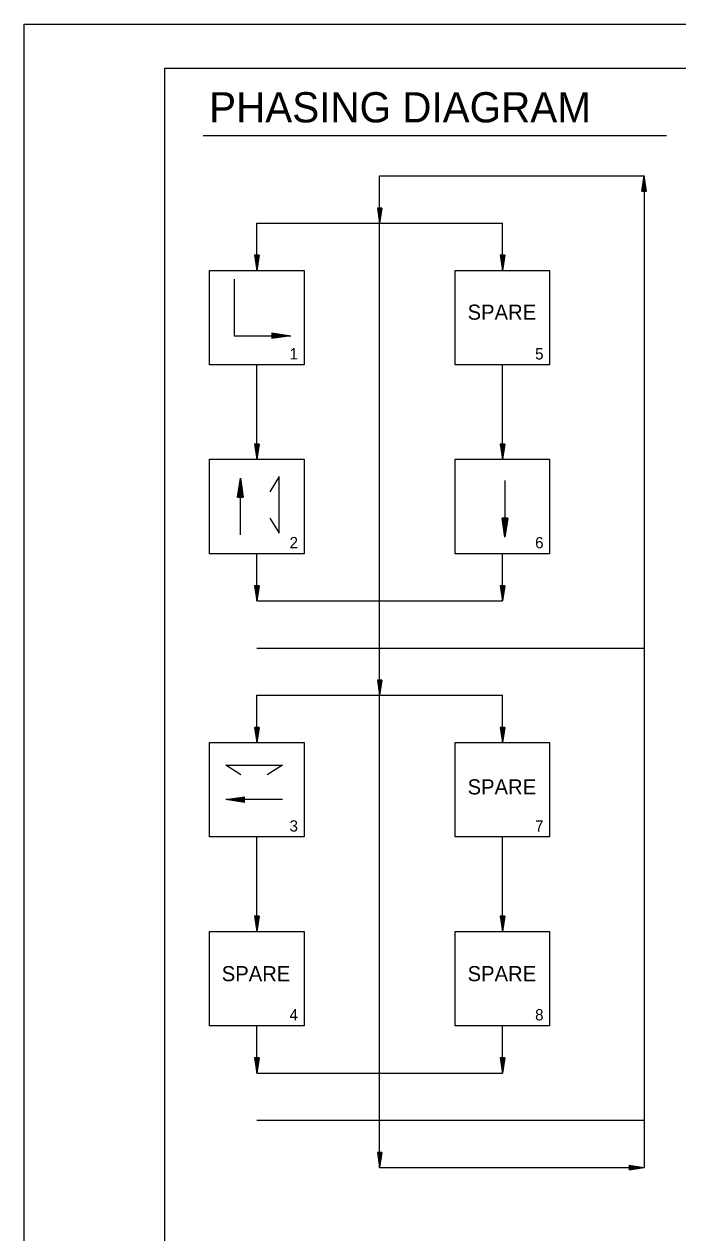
# Model space of a CAD drawing. Extents: x 1709451 to 1710451, y 561684 to 562324.
# Drawn here: x 1709451 to 1709624, y 562004 to 562324 of the extents above; entities that cross this region are included whole.
import ezdxf

# ---------------------------------------------------------------- set-up
doc = ezdxf.new("R2010")
doc.units = 0
for name, color, linetype in [('E_Existing ROW', 7, 'Continuous'), ('R_Alt Surface', 7, 'Continuous'), ('R_Alt Surface Annot', 7, 'Continuous'), ('R_Detour', 7, 'Continuous'), ('R_Detour Annot', 7, 'Continuous')]:
    doc.layers.add(name, color=color, linetype=linetype)

msp = doc.modelspace()

# ---------------------------------------------------------------- linework, layer by layer
at = {"layer": 'E_Existing ROW'}
for p, q in [((1709545.08, 562021.3), (1709545.08, 562283.8)), ((1709545.08, 562283.8), (1709615.08, 562283.8)), ((1709615.08, 562283.8), (1709615.08, 562021.3)), ((1709512.58, 562258.8), (1709512.58, 562271.3)), ((1709512.58, 562271.3), (1709577.58, 562271.3)), ((1709577.58, 562258.8), (1709577.58, 562271.3)), ((1709506.59, 562256.51), (1709506.59, 562241.51)), ((1709516.59, 562242.26), (1709521.59, 562241.51)), ((1709516.59, 562242.26), (1709516.59, 562240.76)), ((1709520.75, 562241.51), (1709516.59, 562242.14)), ((1709516.59, 562242.01), (1709519.89, 562241.51)), ((1709519.06, 562241.51), (1709516.59, 562241.88)), ((1709516.59, 562241.75), (1709518.21, 562241.51)), ((1709506.59, 562241.51), (1709521.59, 562241.51)), ((1709517.38, 562241.51), (1709516.59, 562241.63)), ((1709521.59, 562241.51), (1709516.59, 562240.76)), ((1709516.59, 562240.89), (1709520.75, 562241.51)), ((1709519.89, 562241.51), (1709516.59, 562241.01)), ((1709516.59, 562241.14), (1709519.06, 562241.51)), ((1709518.21, 562241.51), (1709516.59, 562241.27)), ((1709516.59, 562241.39), (1709517.38, 562241.51)), ((1709512.58, 562208.8), (1709512.58, 562233.8)), ((1709577.58, 562208.8), (1709577.58, 562233.8)), ((1709507.48, 562198.76), (1709508.23, 562203.76)), ((1709508.23, 562188.76), (1709508.23, 562203.76)), ((1709508.23, 562203.76), (1709508.98, 562198.76)), ((1709508.23, 562202.93), (1709507.61, 562198.76)), ((1709507.74, 562198.76), (1709508.23, 562202.07)), ((1709508.23, 562201.23), (1709507.86, 562198.76)), ((1709507.99, 562198.76), (1709508.23, 562200.39)), ((1709508.86, 562198.76), (1709508.23, 562202.93)), ((1709508.23, 562202.07), (1709508.73, 562198.76)), ((1709508.61, 562198.76), (1709508.23, 562201.23)), ((1709508.23, 562200.39), (1709508.48, 562198.76)), ((1709578.25, 562203.18), (1709578.25, 562188.18)), ((1709507.48, 562198.76), (1709508.98, 562198.76)), ((1709508.23, 562199.55), (1709508.12, 562198.76)), ((1709508.35, 562198.76), (1709508.23, 562199.55)), ((1709578.25, 562188.18), (1709577.5, 562193.18)), ((1709579, 562193.18), (1709577.5, 562193.18)), ((1709577.62, 562193.18), (1709578.25, 562189.02)), ((1709578.25, 562189.88), (1709577.75, 562193.18)), ((1709577.87, 562193.18), (1709578.25, 562190.71)), ((1709578.25, 562191.56), (1709578, 562193.18)), ((1709578.13, 562193.18), (1709578.25, 562192.39)), ((1709578.25, 562192.39), (1709578.36, 562193.18)), ((1709578.49, 562193.18), (1709578.25, 562191.56)), ((1709578.25, 562190.71), (1709578.62, 562193.18)), ((1709578.74, 562193.18), (1709578.25, 562189.88)), ((1709578.25, 562189.02), (1709578.87, 562193.18)), ((1709579, 562193.18), (1709578.25, 562188.18)), ((1709512.58, 562171.3), (1709512.58, 562183.8)), ((1709577.58, 562171.3), (1709577.58, 562183.8)), ((1709512.58, 562171.3), (1709577.58, 562171.3)), ((1709512.58, 562158.8), (1709615.08, 562158.8)), ((1709512.58, 562146.3), (1709577.58, 562146.3)), ((1709512.58, 562133.8), (1709512.58, 562146.3)), ((1709577.58, 562133.8), (1709577.58, 562146.3)), ((1709504.35, 562118.7), (1709509.35, 562119.45)), ((1709519.35, 562118.7), (1709504.35, 562118.7)), ((1709509.35, 562117.95), (1709504.35, 562118.7)), ((1709509.35, 562119.33), (1709505.19, 562118.7)), ((1709505.19, 562118.7), (1709509.35, 562118.08)), ((1709506.05, 562118.7), (1709509.35, 562119.2)), ((1709509.35, 562118.2), (1709506.05, 562118.7)), ((1709509.35, 562119.07), (1709506.88, 562118.7)), ((1709506.88, 562118.7), (1709509.35, 562118.33)), ((1709507.73, 562118.7), (1709509.35, 562118.95)), ((1709509.35, 562118.46), (1709507.73, 562118.7)), ((1709509.35, 562118.82), (1709508.56, 562118.7)), ((1709508.56, 562118.7), (1709509.35, 562118.58)), ((1709509.35, 562117.95), (1709509.35, 562119.45)), ((1709512.58, 562083.8), (1709512.58, 562108.8)), ((1709577.58, 562083.8), (1709577.58, 562108.8)), ((1709512.58, 562046.3), (1709512.58, 562058.8)), ((1709577.58, 562046.3), (1709577.58, 562058.8)), ((1709512.58, 562046.3), (1709577.58, 562046.3)), ((1709512.58, 562033.8), (1709615.08, 562033.8)), ((1709545.08, 562021.3), (1709615.08, 562021.3))]:
    msp.add_line(p, q, dxfattribs=at)
for points in [[(1709500.08, 562258.8), (1709525.08, 562258.8), (1709525.08, 562233.8), (1709500.08, 562233.8)], [(1709565.08, 562258.8), (1709590.08, 562258.8), (1709590.08, 562233.8), (1709565.08, 562233.8)], [(1709500.08, 562208.8), (1709525.08, 562208.8), (1709525.08, 562183.8), (1709500.08, 562183.8)], [(1709565.08, 562208.8), (1709590.08, 562208.8), (1709590.08, 562183.8), (1709565.08, 562183.8)], [(1709500.08, 562133.8), (1709525.08, 562133.8), (1709525.08, 562108.8), (1709500.08, 562108.8)], [(1709565.08, 562133.8), (1709590.08, 562133.8), (1709590.08, 562108.8), (1709565.08, 562108.8)], [(1709500.08, 562083.8), (1709525.08, 562083.8), (1709525.08, 562058.8), (1709500.08, 562058.8)], [(1709565.08, 562083.8), (1709590.08, 562083.8), (1709590.08, 562058.8), (1709565.08, 562058.8)]]:
    msp.add_lwpolyline(points, close=True, dxfattribs=at)
for points in [[(1709516.03, 562193.21), (1709518.53, 562189.21), (1709518.53, 562204.21), (1709516.03, 562200.21)], [(1709508.35, 562125.27), (1709504.35, 562127.77), (1709519.35, 562127.77), (1709515.35, 562125.27)]]:
    msp.add_lwpolyline(points, dxfattribs=at)
at = {"layer": 'R_Alt Surface'}
for p, q in [((1709488.22, 562312.31), (1710436.76, 562312.31)), ((1709488.22, 561695.93), (1709488.22, 562312.31))]:
    msp.add_line(p, q, dxfattribs=at)
at = {"layer": 'R_Alt Surface Annot'}
msp.add_line((1709451.02, 562324), (1710451.02, 562324), dxfattribs=at)
msp.add_lwpolyline([(1709451, 562324), (1710451.02, 562324), (1710451.02, 561683.98), (1709451, 561683.98)], close=True, dxfattribs=at)
at = {"layer": 'R_Detour'}
msp.add_line((1709498.35, 562294.52), (1709621, 562294.52), dxfattribs=at)
at = {"layer": 'R_Detour Annot'}
for p, q in [((1709614.48, 562279.8), (1709615.08, 562283.8)), ((1709615.68, 562279.8), (1709615.08, 562283.8)), ((1709614.58, 562279.8), (1709615.08, 562283.13)), ((1709614.68, 562279.8), (1709615.08, 562282.45)), ((1709614.78, 562279.8), (1709615.08, 562281.78)), ((1709614.88, 562279.8), (1709615.08, 562281.1)), ((1709614.98, 562279.8), (1709615.08, 562280.43)), ((1709615.58, 562279.8), (1709615.08, 562283.13)), ((1709615.47, 562279.8), (1709615.08, 562282.45)), ((1709615.37, 562279.8), (1709615.08, 562281.78)), ((1709615.27, 562279.8), (1709615.08, 562281.1)), ((1709615.17, 562279.8), (1709615.08, 562280.43)), ((1709614.48, 562279.8), (1709615.68, 562279.8)), ((1709544.48, 562275.3), (1709545.08, 562271.3)), ((1709545.68, 562275.3), (1709544.48, 562275.3)), ((1709544.58, 562275.3), (1709545.08, 562271.97)), ((1709544.68, 562275.3), (1709545.08, 562272.66)), ((1709544.78, 562275.3), (1709545.08, 562273.32)), ((1709544.88, 562275.3), (1709545.08, 562274)), ((1709544.98, 562275.3), (1709545.08, 562274.67)), ((1709545.68, 562275.3), (1709545.08, 562271.3)), ((1709545.27, 562275.3), (1709545.08, 562274)), ((1709545.47, 562275.3), (1709545.08, 562272.66)), ((1709545.58, 562275.3), (1709545.08, 562271.97)), ((1709545.37, 562275.3), (1709545.08, 562273.32)), ((1709545.17, 562275.3), (1709545.08, 562274.67)), ((1709511.98, 562262.8), (1709512.58, 562258.8)), ((1709513.18, 562262.8), (1709511.98, 562262.8)), ((1709512.08, 562262.8), (1709512.58, 562259.47)), ((1709512.18, 562262.8), (1709512.58, 562260.16)), ((1709512.28, 562262.8), (1709512.58, 562260.82)), ((1709512.38, 562262.8), (1709512.58, 562261.5)), ((1709512.48, 562262.8), (1709512.58, 562262.17)), ((1709513.18, 562262.8), (1709512.58, 562258.8)), ((1709512.77, 562262.8), (1709512.58, 562261.5)), ((1709512.97, 562262.8), (1709512.58, 562260.16)), ((1709513.08, 562262.8), (1709512.58, 562259.47)), ((1709512.87, 562262.8), (1709512.58, 562260.82)), ((1709512.67, 562262.8), (1709512.58, 562262.17)), ((1709576.98, 562262.8), (1709577.58, 562258.8)), ((1709578.18, 562262.8), (1709576.98, 562262.8)), ((1709577.08, 562262.8), (1709577.58, 562259.47)), ((1709577.18, 562262.8), (1709577.58, 562260.16)), ((1709577.28, 562262.8), (1709577.58, 562260.82)), ((1709577.38, 562262.8), (1709577.58, 562261.5)), ((1709577.48, 562262.8), (1709577.58, 562262.17)), ((1709578.18, 562262.8), (1709577.58, 562258.8)), ((1709577.77, 562262.8), (1709577.58, 562261.5)), ((1709577.97, 562262.8), (1709577.58, 562260.16)), ((1709578.08, 562262.8), (1709577.58, 562259.47)), ((1709577.87, 562262.8), (1709577.58, 562260.82)), ((1709577.67, 562262.8), (1709577.58, 562262.17)), ((1709511.98, 562212.8), (1709512.58, 562208.8)), ((1709513.18, 562212.8), (1709511.98, 562212.8)), ((1709512.08, 562212.8), (1709512.58, 562209.47)), ((1709512.18, 562212.8), (1709512.58, 562210.16)), ((1709512.28, 562212.8), (1709512.58, 562210.82)), ((1709512.38, 562212.8), (1709512.58, 562211.5)), ((1709512.48, 562212.8), (1709512.58, 562212.17)), ((1709513.18, 562212.8), (1709512.58, 562208.8)), ((1709512.77, 562212.8), (1709512.58, 562211.5)), ((1709512.97, 562212.8), (1709512.58, 562210.16)), ((1709513.08, 562212.8), (1709512.58, 562209.47)), ((1709512.87, 562212.8), (1709512.58, 562210.82)), ((1709512.67, 562212.8), (1709512.58, 562212.17)), ((1709576.98, 562212.8), (1709577.58, 562208.8)), ((1709578.18, 562212.8), (1709576.98, 562212.8)), ((1709577.08, 562212.8), (1709577.58, 562209.47)), ((1709577.18, 562212.8), (1709577.58, 562210.16)), ((1709577.28, 562212.8), (1709577.58, 562210.82)), ((1709577.38, 562212.8), (1709577.58, 562211.5)), ((1709577.48, 562212.8), (1709577.58, 562212.17)), ((1709578.18, 562212.8), (1709577.58, 562208.8)), ((1709577.77, 562212.8), (1709577.58, 562211.5)), ((1709577.97, 562212.8), (1709577.58, 562210.16)), ((1709578.08, 562212.8), (1709577.58, 562209.47)), ((1709577.87, 562212.8), (1709577.58, 562210.82)), ((1709577.67, 562212.8), (1709577.58, 562212.17)), ((1709511.98, 562175.3), (1709512.58, 562171.3)), ((1709513.18, 562175.3), (1709511.98, 562175.3)), ((1709512.08, 562175.3), (1709512.58, 562171.97)), ((1709512.18, 562175.3), (1709512.58, 562172.66)), ((1709512.28, 562175.3), (1709512.58, 562173.32)), ((1709512.38, 562175.3), (1709512.58, 562174)), ((1709512.48, 562175.3), (1709512.58, 562174.67)), ((1709513.18, 562175.3), (1709512.58, 562171.3)), ((1709512.77, 562175.3), (1709512.58, 562174)), ((1709512.97, 562175.3), (1709512.58, 562172.66)), ((1709513.08, 562175.3), (1709512.58, 562171.97)), ((1709512.87, 562175.3), (1709512.58, 562173.32)), ((1709512.67, 562175.3), (1709512.58, 562174.67)), ((1709576.98, 562175.3), (1709577.58, 562171.3)), ((1709578.18, 562175.3), (1709576.98, 562175.3)), ((1709577.08, 562175.3), (1709577.58, 562171.97)), ((1709577.18, 562175.3), (1709577.58, 562172.66)), ((1709577.28, 562175.3), (1709577.58, 562173.32)), ((1709577.38, 562175.3), (1709577.58, 562174)), ((1709577.48, 562175.3), (1709577.58, 562174.67)), ((1709578.18, 562175.3), (1709577.58, 562171.3)), ((1709577.77, 562175.3), (1709577.58, 562174)), ((1709577.97, 562175.3), (1709577.58, 562172.66)), ((1709578.08, 562175.3), (1709577.58, 562171.97)), ((1709577.87, 562175.3), (1709577.58, 562173.32)), ((1709577.67, 562175.3), (1709577.58, 562174.67)), ((1709544.48, 562150.3), (1709545.08, 562146.3)), ((1709545.68, 562150.3), (1709544.48, 562150.3)), ((1709544.58, 562150.3), (1709545.08, 562146.97)), ((1709544.68, 562150.3), (1709545.08, 562147.66)), ((1709544.78, 562150.3), (1709545.08, 562148.32)), ((1709544.88, 562150.3), (1709545.08, 562149)), ((1709544.98, 562150.3), (1709545.08, 562149.67)), ((1709545.68, 562150.3), (1709545.08, 562146.3)), ((1709545.27, 562150.3), (1709545.08, 562149)), ((1709545.47, 562150.3), (1709545.08, 562147.66)), ((1709545.58, 562150.3), (1709545.08, 562146.97)), ((1709545.37, 562150.3), (1709545.08, 562148.32)), ((1709545.17, 562150.3), (1709545.08, 562149.67)), ((1709511.98, 562137.8), (1709512.58, 562133.8)), ((1709513.18, 562137.8), (1709511.98, 562137.8)), ((1709512.08, 562137.8), (1709512.58, 562134.47)), ((1709512.18, 562137.8), (1709512.58, 562135.16)), ((1709512.28, 562137.8), (1709512.58, 562135.82)), ((1709512.38, 562137.8), (1709512.58, 562136.5)), ((1709512.48, 562137.8), (1709512.58, 562137.17)), ((1709513.18, 562137.8), (1709512.58, 562133.8)), ((1709512.77, 562137.8), (1709512.58, 562136.5)), ((1709512.97, 562137.8), (1709512.58, 562135.16)), ((1709513.08, 562137.8), (1709512.58, 562134.47)), ((1709512.87, 562137.8), (1709512.58, 562135.82)), ((1709512.67, 562137.8), (1709512.58, 562137.17)), ((1709576.98, 562137.8), (1709577.58, 562133.8)), ((1709578.18, 562137.8), (1709576.98, 562137.8)), ((1709577.08, 562137.8), (1709577.58, 562134.47)), ((1709577.18, 562137.8), (1709577.58, 562135.16)), ((1709577.28, 562137.8), (1709577.58, 562135.82)), ((1709577.38, 562137.8), (1709577.58, 562136.5)), ((1709577.48, 562137.8), (1709577.58, 562137.17)), ((1709578.18, 562137.8), (1709577.58, 562133.8)), ((1709577.77, 562137.8), (1709577.58, 562136.5)), ((1709577.97, 562137.8), (1709577.58, 562135.16)), ((1709578.08, 562137.8), (1709577.58, 562134.47)), ((1709577.87, 562137.8), (1709577.58, 562135.82)), ((1709577.67, 562137.8), (1709577.58, 562137.17)), ((1709511.98, 562087.8), (1709512.58, 562083.8)), ((1709513.18, 562087.8), (1709511.98, 562087.8)), ((1709512.08, 562087.8), (1709512.58, 562084.47)), ((1709512.18, 562087.8), (1709512.58, 562085.16)), ((1709512.28, 562087.8), (1709512.58, 562085.82)), ((1709512.38, 562087.8), (1709512.58, 562086.5)), ((1709512.48, 562087.8), (1709512.58, 562087.17)), ((1709513.18, 562087.8), (1709512.58, 562083.8)), ((1709512.77, 562087.8), (1709512.58, 562086.5)), ((1709512.97, 562087.8), (1709512.58, 562085.16)), ((1709513.08, 562087.8), (1709512.58, 562084.47)), ((1709512.87, 562087.8), (1709512.58, 562085.82)), ((1709512.67, 562087.8), (1709512.58, 562087.17)), ((1709576.98, 562087.8), (1709577.58, 562083.8)), ((1709578.18, 562087.8), (1709576.98, 562087.8)), ((1709577.08, 562087.8), (1709577.58, 562084.47)), ((1709577.18, 562087.8), (1709577.58, 562085.16)), ((1709577.28, 562087.8), (1709577.58, 562085.82)), ((1709577.38, 562087.8), (1709577.58, 562086.5)), ((1709577.48, 562087.8), (1709577.58, 562087.17)), ((1709578.18, 562087.8), (1709577.58, 562083.8)), ((1709577.77, 562087.8), (1709577.58, 562086.5)), ((1709577.97, 562087.8), (1709577.58, 562085.16)), ((1709578.08, 562087.8), (1709577.58, 562084.47)), ((1709577.87, 562087.8), (1709577.58, 562085.82)), ((1709577.67, 562087.8), (1709577.58, 562087.17)), ((1709511.98, 562050.3), (1709512.58, 562046.3)), ((1709513.18, 562050.3), (1709511.98, 562050.3)), ((1709512.08, 562050.3), (1709512.58, 562046.97)), ((1709512.18, 562050.3), (1709512.58, 562047.66)), ((1709512.28, 562050.3), (1709512.58, 562048.32)), ((1709512.38, 562050.3), (1709512.58, 562049)), ((1709512.48, 562050.3), (1709512.58, 562049.67)), ((1709513.18, 562050.3), (1709512.58, 562046.3)), ((1709512.77, 562050.3), (1709512.58, 562049)), ((1709512.97, 562050.3), (1709512.58, 562047.66)), ((1709513.08, 562050.3), (1709512.58, 562046.97)), ((1709512.87, 562050.3), (1709512.58, 562048.32)), ((1709512.67, 562050.3), (1709512.58, 562049.67)), ((1709576.98, 562050.3), (1709577.58, 562046.3)), ((1709578.18, 562050.3), (1709576.98, 562050.3)), ((1709577.08, 562050.3), (1709577.58, 562046.97)), ((1709577.18, 562050.3), (1709577.58, 562047.66)), ((1709577.28, 562050.3), (1709577.58, 562048.32)), ((1709577.38, 562050.3), (1709577.58, 562049)), ((1709577.48, 562050.3), (1709577.58, 562049.67)), ((1709578.18, 562050.3), (1709577.58, 562046.3)), ((1709577.77, 562050.3), (1709577.58, 562049)), ((1709577.97, 562050.3), (1709577.58, 562047.66)), ((1709578.08, 562050.3), (1709577.58, 562046.97)), ((1709577.87, 562050.3), (1709577.58, 562048.32)), ((1709577.67, 562050.3), (1709577.58, 562049.67)), ((1709544.48, 562025.3), (1709545.08, 562021.3)), ((1709545.68, 562025.3), (1709544.48, 562025.3)), ((1709544.58, 562025.3), (1709545.08, 562021.97)), ((1709544.68, 562025.3), (1709545.08, 562022.66)), ((1709544.78, 562025.3), (1709545.08, 562023.32)), ((1709544.88, 562025.3), (1709545.08, 562024)), ((1709544.98, 562025.3), (1709545.08, 562024.67)), ((1709545.68, 562025.3), (1709545.08, 562021.3)), ((1709545.27, 562025.3), (1709545.08, 562024)), ((1709545.47, 562025.3), (1709545.08, 562022.66)), ((1709545.58, 562025.3), (1709545.08, 562021.97)), ((1709545.37, 562025.3), (1709545.08, 562023.32)), ((1709545.17, 562025.3), (1709545.08, 562024.67)), ((1709611.08, 562021.9), (1709615.08, 562021.3)), ((1709611.08, 562021.9), (1709611.08, 562020.7)), ((1709611.08, 562021.8), (1709614.41, 562021.3)), ((1709611.08, 562021.7), (1709613.72, 562021.3)), ((1709611.08, 562021.6), (1709613.05, 562021.3)), ((1709611.08, 562021.5), (1709612.38, 562021.3)), ((1709611.08, 562021.4), (1709611.71, 562021.3)), ((1709611.08, 562020.7), (1709615.08, 562021.3)), ((1709611.08, 562021.11), (1709612.38, 562021.3)), ((1709611.08, 562020.9), (1709613.72, 562021.3)), ((1709611.08, 562020.8), (1709614.41, 562021.3)), ((1709611.08, 562021), (1709613.05, 562021.3)), ((1709611.08, 562021.21), (1709611.71, 562021.3))]:
    msp.add_line(p, q, dxfattribs=at)

# ---------------------------------------------------------------- texts
at = {"layer": 'E_Existing ROW'}
for p in [(1709568.36, 562245.75), (1709568.36, 562120.06), (1709503.29, 562070.61), (1709568.36, 562070.61)]:
    msp.add_text('SPARE', height=4, dxfattribs=at).set_placement(p)
at = {"layer": 'R_Detour'}
for s, height, p in [('PHASING DIAGRAM', 8, (1709499.95, 562297.99)), ('1', 3, (1709521.23, 562235.22)), ('5', 3, (1709586.23, 562235.22)), ('2', 3, (1709521.23, 562185.22)), ('6', 3, (1709586.23, 562185.22)), ('3', 3, (1709521.23, 562110.22)), ('7', 3, (1709586.23, 562110.22)), ('4', 3, (1709521.23, 562060.22)), ('8', 3, (1709586.23, 562060.22))]:
    msp.add_text(s, height=height, dxfattribs=at).set_placement(p)

doc.saveas('drawing.dxf')
